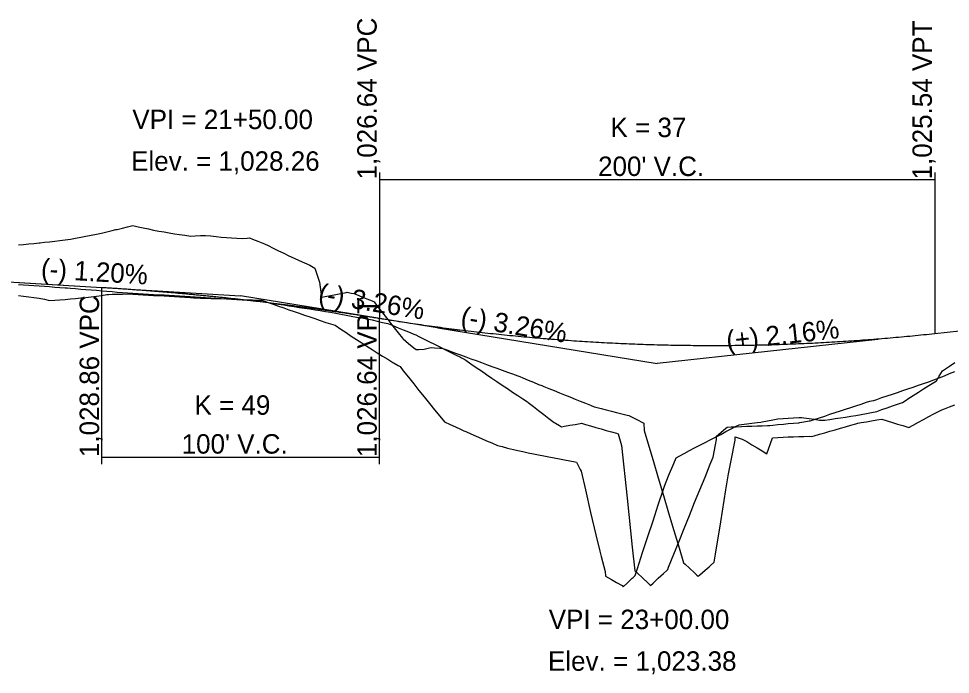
# Model space of a CAD drawing. Extents: x 1590191 to 1593577, y 1108634 to 1115609.
# Drawn here: x 1591349 to 1591684.7, y 1114898.4 to 1115134.6 of the extents above; entities that cross this region are included whole.
import ezdxf

# ---------------------------------------------------------------- set-up
doc = ezdxf.new("R2010")
doc.units = 0
for name, color, linetype in [('BR_EXIST_GROUND_LT', 7, 'Continuous'), ('BR_EXIST_GROUND_RT', 7, 'Continuous'), ('RD_DDB_GradeTX', 7, 'Continuous'), ('RD_DDB_Profile_EX', 7, 'Continuous'), ('RD_DDB_Profile_Lbl', 7, 'Continuous'), ('RD_DDB_Profile_PR', 7, 'Continuous'), ('RD_DDB_StripGrade', 7, 'Continuous'), ('RD_DDB_VCLbl', 7, 'Continuous')]:
    doc.layers.add(name, color=color, linetype=linetype)

msp = doc.modelspace()

# ---------------------------------------------------------------- linework, layer by layer
at = {"layer": 'BR_EXIST_GROUND_LT'}
msp.add_lwpolyline([(1591348.93, 1115034.88), (1591350.81, 1115034.64), (1591352.68, 1115034.4), (1591354.56, 1115034.18), (1591356.43, 1115033.94), (1591358.3, 1115033.49), (1591360.18, 1115033.11), (1591362.05, 1115033.22), (1591363.93, 1115033.34), (1591365.8, 1115033.48), (1591367.67, 1115033.64), (1591369.55, 1115033.81), (1591371.42, 1115034), (1591373.3, 1115034.2), (1591375.17, 1115034.42), (1591377.04, 1115034.66), (1591378.92, 1115034.91), (1591380.79, 1115035.18), (1591381.45, 1115035.28), (1591382.67, 1115035.3), (1591384.54, 1115035.34), (1591386.41, 1115035.38), (1591388.29, 1115035.42), (1591390.16, 1115035.31), (1591392.04, 1115035.2), (1591393.91, 1115035.09), (1591395.78, 1115035), (1591397.66, 1115034.91), (1591399.53, 1115034.83), (1591401.41, 1115034.75), (1591401.93, 1115034.74), (1591403.28, 1115034.63), (1591405.15, 1115034.49), (1591407.03, 1115034.35), (1591408.9, 1115034.22), (1591410.78, 1115034.1), (1591412.08, 1115034.01), (1591412.65, 1115034), (1591414.52, 1115033.94), (1591416.4, 1115033.88), (1591418.27, 1115033.83), (1591420.15, 1115033.79), (1591422.02, 1115033.75), (1591423.89, 1115033.66), (1591425.77, 1115033.58), (1591427.64, 1115033.5), (1591429.52, 1115033.43), (1591431.39, 1115033.36), (1591433.26, 1115033.3), (1591435.14, 1115033.24), (1591436.14, 1115033.22), (1591436.59, 1115033.21), (1591437.01, 1115033.06), (1591438.89, 1115032.39), (1591440.76, 1115031.72), (1591442.63, 1115031.06), (1591444.51, 1115030.4), (1591446.38, 1115029.75), (1591448.26, 1115029.1), (1591450.13, 1115028.46), (1591452, 1115027.82), (1591453.88, 1115027.19), (1591455.75, 1115026.56), (1591457.63, 1115025.89), (1591459.64, 1115025.18), (1591461.37, 1115024.67), (1591463.02, 1115024.18), (1591465.12, 1115022.74), (1591467, 1115021.48), (1591468.87, 1115020.23), (1591470.74, 1115019), (1591472.62, 1115017.79), (1591474.49, 1115016.6), (1591476.37, 1115015.43), (1591476.69, 1115015.22), (1591478.24, 1115014.24), (1591480.11, 1115013.07), (1591481.99, 1115011.92), (1591483.86, 1115010.78), (1591484.28, 1115010.54), (1591485.74, 1115009.69), (1591486.45, 1115009.27), (1591487.61, 1115007.78), (1591489.48, 1115005.39), (1591491.36, 1115003.02), (1591493.23, 1115000.66), (1591495.11, 1114998.32), (1591496.98, 1114996), (1591498.85, 1114993.7), (1591500.73, 1114991.41), (1591502.45, 1114989.33), (1591504.48, 1114988.41), (1591506.35, 1114987.55), (1591508.22, 1114986.71), (1591509.46, 1114986.16), (1591510.1, 1114985.87), (1591511.97, 1114985.04), (1591513.85, 1114984.21), (1591515.72, 1114983.39), (1591517.59, 1114982.57), (1591519.47, 1114981.77), (1591521.59, 1114980.86), (1591523.22, 1114980.42), (1591525.09, 1114979.93), (1591527.24, 1114979.37), (1591528.84, 1114979.03), (1591530.71, 1114978.63), (1591532.59, 1114978.23), (1591534.46, 1114977.85), (1591536.33, 1114977.46), (1591538.21, 1114977.08), (1591540.08, 1114976.71), (1591541.96, 1114976.34), (1591543.83, 1114975.98), (1591545.7, 1114975.62), (1591547.58, 1114975.27), (1591549.45, 1114974.92), (1591549.98, 1114974.83), (1591551.33, 1114972.16), (1591551.64, 1114971.54), (1591553.2, 1114964.82), (1591555.07, 1114956.75), (1591556.95, 1114948.7), (1591558.34, 1114942.75), (1591558.82, 1114940.9), (1591560.27, 1114935.41), (1591560.43, 1114933.79), (1591562.57, 1114932.57), (1591564.44, 1114931.5), (1591566.38, 1114930.4), (1591566.84, 1114929.95), (1591568.19, 1114931.23), (1591570.07, 1114933), (1591570.41, 1114933.33), (1591571.13, 1114934.06), (1591571.94, 1114936.53), (1591573.81, 1114942.28), (1591575.69, 1114948.01), (1591577.56, 1114953.73), (1591579.44, 1114959.44), (1591581.31, 1114965.13), (1591581.67, 1114966.23), (1591583.18, 1114969.89), (1591585.06, 1114974.41), (1591585.87, 1114976.37), (1591586.93, 1114976.95), (1591588.81, 1114977.99), (1591590.68, 1114979.02), (1591592.55, 1114979.99), (1591594.43, 1114980.96), (1591596.3, 1114981.93), (1591598.18, 1114982.9), (1591600.05, 1114983.87), (1591601.92, 1114984.85), (1591603.8, 1114985.82), (1591605.67, 1114986.79), (1591607.55, 1114987.77), (1591608.58, 1114988.3), (1591609.42, 1114988.41), (1591611.29, 1114988.65), (1591613.17, 1114988.88), (1591615.04, 1114989.12), (1591616.43, 1114989.29), (1591616.92, 1114989.38), (1591618.79, 1114989.73), (1591620.66, 1114990.07), (1591622.57, 1114990.42), (1591624.41, 1114990.54), (1591626.29, 1114990.66), (1591628.16, 1114990.78), (1591630.03, 1114990.9), (1591631.05, 1114990.96), (1591631.91, 1114990.84), (1591633.78, 1114990.57), (1591635.66, 1114990.3), (1591637.53, 1114990.02), (1591638.94, 1114989.92), (1591639.4, 1114989.98), (1591641.28, 1114990.25), (1591643.15, 1114990.53), (1591645.03, 1114990.8), (1591646.9, 1114991.08), (1591648.77, 1114991.37), (1591650.65, 1114991.67), (1591652.52, 1114992.03), (1591654.4, 1114992.39), (1591656.27, 1114992.76), (1591658.14, 1114993.14), (1591660.02, 1114993.79), (1591661.89, 1114994.45), (1591663.77, 1114995.1), (1591665.64, 1114995.76), (1591667.39, 1114996.36), (1591668.69, 1114997.22), (1591669.39, 1114997.67), (1591671.26, 1114998.88), (1591673.14, 1115000.08), (1591675.01, 1115001.26), (1591676.88, 1115002.42), (1591678.76, 1115003.58), (1591679.63, 1115004.1), (1591680.63, 1115005.78), (1591681.82, 1115007.75), (1591682.51, 1115008.22), (1591684.38, 1115009.46), (1591686.25, 1115010.68)], dxfattribs=at)
at = {"layer": 'BR_EXIST_GROUND_RT'}
msp.add_lwpolyline([(1591348.93, 1115053.14), (1591350.81, 1115053.28), (1591352.68, 1115053.45), (1591354.56, 1115053.63), (1591356.43, 1115053.83), (1591356.79, 1115053.87), (1591358.3, 1115054.02), (1591360.18, 1115054.22), (1591362.05, 1115054.44), (1591363.93, 1115054.67), (1591365.8, 1115054.92), (1591367.69, 1115055.19), (1591369.55, 1115055.51), (1591371.42, 1115055.85), (1591373.3, 1115056.2), (1591375.17, 1115056.57), (1591377.04, 1115056.96), (1591378.92, 1115057.37), (1591380.79, 1115057.79), (1591382.67, 1115058.23), (1591384.1, 1115058.58), (1591384.54, 1115058.68), (1591386.41, 1115059.13), (1591388.29, 1115059.59), (1591390.16, 1115060.04), (1591392.04, 1115059.62), (1591393.91, 1115059.21), (1591395.78, 1115058.82), (1591397.66, 1115058.44), (1591399.53, 1115058.09), (1591401.41, 1115057.75), (1591403.28, 1115057.42), (1591405.15, 1115057.12), (1591407.03, 1115056.83), (1591408.9, 1115056.56), (1591411.04, 1115056.27), (1591412.65, 1115056.33), (1591414.52, 1115056.42), (1591416.4, 1115056.51), (1591418.27, 1115056.3), (1591420.15, 1115056.11), (1591422.02, 1115055.93), (1591423.89, 1115055.77), (1591425.77, 1115055.62), (1591427.64, 1115055.48), (1591429.56, 1115055.36), (1591431.39, 1115055.55), (1591432.17, 1115055.64), (1591433.26, 1115055.2), (1591435.14, 1115054.44), (1591437.01, 1115053.71), (1591437.57, 1115053.49), (1591438.89, 1115052.83), (1591440.76, 1115051.9), (1591442.63, 1115050.99), (1591444.51, 1115050.08), (1591446.38, 1115049.19), (1591448.26, 1115048.31), (1591450.13, 1115047.44), (1591452, 1115046.58), (1591453.88, 1115045.73), (1591455.75, 1115044.65), (1591457.47, 1115039.69), (1591458.14, 1115034.21), (1591459.5, 1115034.47), (1591461.37, 1115034.83), (1591463.25, 1115035.2), (1591465.12, 1115035.58), (1591467, 1115035.97), (1591467.37, 1115036.05), (1591468.87, 1115035.75), (1591469.78, 1115035.57), (1591470.74, 1115035.18), (1591472.62, 1115034.44), (1591474.49, 1115033.7), (1591476.37, 1115032.97), (1591477.13, 1115032.53), (1591478.24, 1115031.08), (1591480.11, 1115028.64), (1591481.99, 1115026.22), (1591483.86, 1115023.81), (1591485.74, 1115021.43), (1591487.27, 1115019.49), (1591487.61, 1115019.2), (1591489.48, 1115017.61), (1591491.36, 1115016.04), (1591492.18, 1115015.36), (1591493.23, 1115015.41), (1591495.11, 1115015.51), (1591496.98, 1115015.97), (1591497.71, 1115016.15), (1591498.85, 1115016.06), (1591500.73, 1115015.9), (1591501.49, 1115015.93), (1591502.6, 1115015.53), (1591503.59, 1115015.18), (1591504.48, 1115014.85), (1591506.35, 1115014.15), (1591507.09, 1115013.88), (1591508.22, 1115013.46), (1591510.1, 1115012.77), (1591511.97, 1115012.09), (1591513.85, 1115011.4), (1591515.72, 1115010.71), (1591517.59, 1115010.03), (1591519.47, 1115009.34), (1591521.34, 1115008.65), (1591523.22, 1115007.97), (1591525.09, 1115007.28), (1591526.96, 1115006.59), (1591528.84, 1115005.91), (1591529.57, 1115005.64), (1591530.71, 1115005.17), (1591532.59, 1115004.4), (1591534.46, 1115003.63), (1591536.33, 1115002.86), (1591537.48, 1115002.39), (1591538.21, 1115002.1), (1591540.08, 1115001.35), (1591541.96, 1115000.59), (1591543.83, 1114999.84), (1591545.7, 1114999.08), (1591547.58, 1114998.33), (1591549.45, 1114997.58), (1591551.33, 1114996.82), (1591553.2, 1114996.07), (1591555.07, 1114995.32), (1591556.34, 1114994.81), (1591556.95, 1114994.65), (1591558.82, 1114994.18), (1591560.7, 1114993.7), (1591562.57, 1114993.23), (1591564.44, 1114992.76), (1591566.32, 1114992.28), (1591568.19, 1114991.81), (1591568.89, 1114991.63), (1591570.07, 1114991.02), (1591571.94, 1114990.05), (1591573.81, 1114989.08), (1591574.25, 1114988.85), (1591574.38, 1114986.24), (1591575.69, 1114981.82), (1591577.56, 1114975.49), (1591579.44, 1114969.17), (1591581.31, 1114962.86), (1591583.18, 1114956.56), (1591585.06, 1114950.26), (1591586.93, 1114943.97), (1591588.49, 1114938.58), (1591589.08, 1114938.05), (1591590.68, 1114936.6), (1591592.55, 1114934.92), (1591593.39, 1114934.17), (1591593.86, 1114933.73), (1591594.43, 1114934.23), (1591596.3, 1114935.88), (1591597.74, 1114937.15), (1591598.18, 1114937.54), (1591599.57, 1114938.77), (1591600.05, 1114941.75), (1591601.92, 1114953.35), (1591603.8, 1114964.9), (1591604.73, 1114970.61), (1591605.67, 1114975.45), (1591607.1, 1114982.74), (1591607.16, 1114983.91), (1591607.55, 1114983.8), (1591609.68, 1114983.17), (1591611.29, 1114982.23), (1591613.17, 1114981.13), (1591615.04, 1114980.01), (1591616.92, 1114978.87), (1591618.54, 1114977.87), (1591620.6, 1114983.65), (1591622.54, 1114983.74), (1591624.41, 1114983.82), (1591626.29, 1114983.9), (1591628.16, 1114983.97), (1591630.03, 1114984.04), (1591631.91, 1114984.11), (1591633.78, 1114984.15), (1591634.73, 1114984.05), (1591635.66, 1114984.33), (1591637.53, 1114984.88), (1591639.4, 1114985.43), (1591641.28, 1114985.98), (1591643.15, 1114986.52), (1591645.03, 1114987.06), (1591646.9, 1114987.59), (1591648.77, 1114988.12), (1591650.65, 1114988.65), (1591651.38, 1114988.85), (1591652.52, 1114989.06), (1591654.4, 1114989.39), (1591656.27, 1114989.72), (1591658.14, 1114990.04), (1591660.02, 1114990.32), (1591661.89, 1114989.74), (1591663.77, 1114989.16), (1591665.64, 1114988.57), (1591667.51, 1114987.98), (1591669.68, 1114987.29), (1591671.26, 1114988.18), (1591673.14, 1114989.21), (1591675.01, 1114990.23), (1591676.88, 1114991.23), (1591678.76, 1114992.22), (1591680.63, 1114993.2), (1591681.58, 1114993.69), (1591682.51, 1114994.06), (1591684.38, 1114994.79), (1591686.25, 1114995.52)], dxfattribs=at)
at = {"layer": 'RD_DDB_GradeTX'}
for p, q in [((1591349.16, 1115039.59), (1591429.01, 1115034.79)), ((1591507.97, 1115021.94), (1591429.01, 1115034.79)), ((1591500.05, 1115023.23), (1591579.01, 1115010.38)), ((1591658.55, 1115018.98), (1591579.01, 1115010.38))]:
    msp.add_line(p, q, dxfattribs=at)
at = {"layer": 'RD_DDB_Profile_EX'}
msp.add_lwpolyline([(1591348.93, 1115038.86), (1591350.81, 1115038.73), (1591352.68, 1115038.59), (1591354.56, 1115038.46), (1591356.43, 1115038.32), (1591358.33, 1115038.18), (1591360.18, 1115038.05), (1591362.05, 1115037.91), (1591363.93, 1115037.78), (1591365.8, 1115037.64), (1591366.58, 1115037.58), (1591367.67, 1115037.5), (1591369.55, 1115037.35), (1591371.42, 1115037.2), (1591373.3, 1115037.04), (1591375.17, 1115036.89), (1591377.04, 1115036.73), (1591379.1, 1115036.56), (1591380.79, 1115036.42), (1591382.67, 1115036.27), (1591384.54, 1115036.12), (1591386.41, 1115035.96), (1591388.29, 1115035.8), (1591389.7, 1115035.68), (1591390.16, 1115035.66), (1591392.04, 1115035.56), (1591393.91, 1115035.46), (1591395.78, 1115035.36), (1591397.66, 1115035.26), (1591399.53, 1115035.15), (1591400.76, 1115035.08), (1591401.41, 1115035.05), (1591403.28, 1115034.94), (1591405.15, 1115034.83), (1591407.03, 1115034.72), (1591408.9, 1115034.61), (1591410.78, 1115034.5), (1591412.65, 1115034.39), (1591414.67, 1115034.26), (1591416.4, 1115034.15), (1591418.27, 1115034.03), (1591420.15, 1115033.9), (1591422.02, 1115033.78), (1591423.89, 1115033.65), (1591425.77, 1115033.53), (1591427.64, 1115033.4), (1591429.52, 1115033.27), (1591431.39, 1115033.14), (1591433.26, 1115033.01), (1591435.25, 1115032.87), (1591437.01, 1115032.6), (1591438.89, 1115032.32), (1591440.76, 1115032.04), (1591442.63, 1115031.75), (1591444.51, 1115031.47), (1591446.38, 1115031.18), (1591448.26, 1115030.89), (1591450.13, 1115030.6), (1591452, 1115030.31), (1591453.88, 1115030.01), (1591455.84, 1115029.7), (1591457.63, 1115029.44), (1591459.52, 1115029.15), (1591461.37, 1115028.84), (1591463.28, 1115028.51), (1591465.12, 1115028.17), (1591467, 1115027.82), (1591468.87, 1115027.46), (1591470.74, 1115027.11), (1591472.62, 1115026.76), (1591474.49, 1115026.41), (1591476.37, 1115026.05), (1591478.24, 1115025.62), (1591480.11, 1115025.19), (1591481.99, 1115024.75), (1591483.86, 1115024), (1591485.74, 1115023.25), (1591487.61, 1115022.5), (1591489.48, 1115021.74), (1591491.36, 1115020.99), (1591492.09, 1115020.7), (1591493.23, 1115020.12), (1591495.11, 1115019.18), (1591496.98, 1115018.23), (1591498.85, 1115017.29), (1591500.73, 1115016.35), (1591502.6, 1115015.41), (1591504.48, 1115014.47), (1591506.35, 1115013.53), (1591508.22, 1115012.61), (1591508.55, 1115012.47), (1591509.78, 1115011.82), (1591510.1, 1115011.59), (1591511.97, 1115010.28), (1591513.85, 1115008.97), (1591515.72, 1115007.67), (1591517.59, 1115006.38), (1591519.47, 1115005.1), (1591521.34, 1115003.83), (1591523.22, 1115002.57), (1591525.09, 1115001.31), (1591526.96, 1115000.06), (1591528.84, 1114998.83), (1591530.71, 1114997.6), (1591532.28, 1114996.57), (1591532.59, 1114996.34), (1591534.46, 1114994.88), (1591536.33, 1114993.44), (1591538.21, 1114992.01), (1591540.08, 1114990.58), (1591541.96, 1114989.16), (1591542.4, 1114988.83), (1591543.83, 1114988.01), (1591544.54, 1114987.61), (1591545.7, 1114987.8), (1591547.58, 1114988.11), (1591549.45, 1114988.42), (1591551.33, 1114988.74), (1591551.77, 1114988.82), (1591553.2, 1114988.4), (1591555.07, 1114987.86), (1591556.95, 1114987.32), (1591558.82, 1114986.79), (1591560.7, 1114986.27), (1591562.57, 1114985.75), (1591564.44, 1114985.24), (1591565.02, 1114985.08), (1591566.18, 1114980.89), (1591568.19, 1114961.91), (1591570.07, 1114944.23), (1591570.98, 1114935.64), (1591571.35, 1114935.44), (1591571.94, 1114934.88), (1591573.81, 1114933.13), (1591575.69, 1114931.37), (1591576.68, 1114930.45), (1591577.56, 1114931.29), (1591577.93, 1114931.65), (1591579.44, 1114933.03), (1591581.31, 1114934.74), (1591582.5, 1114935.83), (1591582.86, 1114936.17), (1591583.18, 1114936.98), (1591585.06, 1114941.67), (1591586.93, 1114946.34), (1591588.81, 1114951), (1591590.68, 1114955.64), (1591592.55, 1114960.27), (1591594.43, 1114964.88), (1591596.3, 1114969.48), (1591598.18, 1114974.06), (1591599.21, 1114976.58), (1591600.05, 1114981.1), (1591600.4, 1114982.98), (1591600.45, 1114984.23), (1591601.92, 1114985.47), (1591603.8, 1114987.05), (1591604.29, 1114987.46), (1591605.67, 1114987.52), (1591607.55, 1114987.6), (1591609.42, 1114987.67), (1591611.29, 1114987.75), (1591613.17, 1114987.82), (1591615.04, 1114987.9), (1591616.92, 1114987.97), (1591618.79, 1114988.05), (1591619.65, 1114988.08), (1591620.66, 1114988.18), (1591622.54, 1114988.37), (1591624.54, 1114988.57), (1591626.29, 1114988.72), (1591628.16, 1114988.88), (1591630.03, 1114989.04), (1591630.4, 1114989.07), (1591631.91, 1114989.34), (1591633.78, 1114989.66), (1591634.18, 1114989.73), (1591635.66, 1114990.22), (1591637.53, 1114990.83), (1591639.4, 1114991.45), (1591641.28, 1114992.07), (1591643.15, 1114992.69), (1591645.03, 1114993.3), (1591646.9, 1114993.92), (1591648.77, 1114994.54), (1591650.65, 1114995.16), (1591652.52, 1114995.78), (1591654.4, 1114996.39), (1591655.69, 1114996.82), (1591656.27, 1114996.93), (1591657.04, 1114997.08), (1591658.14, 1114997.45), (1591660.02, 1114998.08), (1591661.89, 1114998.71), (1591663.77, 1114999.34), (1591665.64, 1114999.97), (1591667.51, 1115000.61), (1591669.39, 1115001.24), (1591671.26, 1115001.87), (1591673.14, 1115002.51), (1591675.01, 1115003.15), (1591676.88, 1115003.79), (1591678.36, 1115004.32), (1591678.76, 1115004.48), (1591680.63, 1115005.23), (1591682.51, 1115005.98), (1591684.38, 1115006.73), (1591686.25, 1115007.48)], dxfattribs=at)
at = {"layer": 'RD_DDB_Profile_PR'}
for p, q in [((1591199.01, 1115048.59), (1591379.01, 1115037.79)), ((1591679.01, 1115021.19), (1591829.01, 1115037.41))]:
    msp.add_line(p, q, dxfattribs=at)
for points in [[(1591379.01, 1115037.79), (1591381.01, 1115037.67), (1591383.01, 1115037.55), (1591385.01, 1115037.42), (1591387.01, 1115037.28), (1591389.01, 1115037.14), (1591391.01, 1115037), (1591393.01, 1115036.85), (1591395.01, 1115036.7), (1591397.01, 1115036.55), (1591399.01, 1115036.39), (1591401.01, 1115036.23), (1591403.01, 1115036.06), (1591405.01, 1115035.89), (1591407.01, 1115035.71), (1591409.01, 1115035.53), (1591411.01, 1115035.35), (1591413.01, 1115035.16), (1591415.01, 1115034.97), (1591417.01, 1115034.77), (1591419.01, 1115034.57), (1591421.01, 1115034.37), (1591423.01, 1115034.16), (1591425.01, 1115033.95), (1591427.01, 1115033.73), (1591429.01, 1115033.51), (1591431.01, 1115033.29), (1591433.01, 1115033.06), (1591435.01, 1115032.82), (1591437.01, 1115032.59), (1591439.01, 1115032.34), (1591441.01, 1115032.1), (1591443.01, 1115031.85), (1591445.01, 1115031.6), (1591447.01, 1115031.34), (1591449.01, 1115031.08), (1591451.01, 1115030.81), (1591453.01, 1115030.54), (1591455.01, 1115030.27), (1591457.01, 1115029.99), (1591459.01, 1115029.71), (1591461.01, 1115029.42), (1591463.01, 1115029.13), (1591465.01, 1115028.83), (1591467.01, 1115028.54), (1591469.01, 1115028.23), (1591471.01, 1115027.93), (1591473.01, 1115027.61), (1591475.01, 1115027.3), (1591477.01, 1115026.98), (1591479.01, 1115026.66)], [(1591479.01, 1115026.66), (1591483.01, 1115026.02), (1591487.01, 1115025.4), (1591491.01, 1115024.8), (1591495.01, 1115024.23), (1591499.01, 1115023.67), (1591503.01, 1115023.14), (1591507.01, 1115022.63), (1591511.01, 1115022.14), (1591515.01, 1115021.67), (1591519.01, 1115021.23), (1591523.01, 1115020.81), (1591527.01, 1115020.4), (1591531.01, 1115020.02), (1591535.01, 1115019.67), (1591539.01, 1115019.33), (1591543.01, 1115019.01), (1591547.01, 1115018.72), (1591551.01, 1115018.45), (1591555.01, 1115018.2), (1591559.01, 1115017.97), (1591563.01, 1115017.76), (1591567.01, 1115017.58), (1591571.01, 1115017.41), (1591575.01, 1115017.27), (1591579.01, 1115017.15), (1591583.01, 1115017.05), (1591587.01, 1115016.98), (1591591.01, 1115016.92), (1591595.01, 1115016.89), (1591599.01, 1115016.88), (1591603.01, 1115016.89), (1591607.01, 1115016.92), (1591611.01, 1115016.97), (1591615.01, 1115017.05), (1591619.01, 1115017.14), (1591623.01, 1115017.26), (1591627.01, 1115017.4), (1591631.01, 1115017.56), (1591635.01, 1115017.74), (1591639.01, 1115017.95), (1591643.01, 1115018.18), (1591647.01, 1115018.42), (1591651.01, 1115018.69), (1591655.01, 1115018.99), (1591659.01, 1115019.3), (1591663.01, 1115019.63), (1591667.01, 1115019.99), (1591671.01, 1115020.37), (1591675.01, 1115020.77), (1591679.01, 1115021.19)]]:
    msp.add_spline(points, degree=3, dxfattribs=at)
at = {"layer": 'RD_DDB_VCLbl'}
for p, q in [((1591479.01, 1115079.16), (1591479.01, 1115026.66)), ((1591679.01, 1115079.16), (1591679.01, 1115021.19)), ((1591479.01, 1115076.66), (1591679.01, 1115076.66)), ((1591379.01, 1114974.16), (1591379.01, 1115037.79)), ((1591479.01, 1114974.16), (1591479.01, 1115026.66)), ((1591379.01, 1114976.66), (1591479.01, 1114976.66))]:
    msp.add_line(p, q, dxfattribs=at)

# ---------------------------------------------------------------- texts
at = {"layer": 'RD_DDB_GradeTX'}
for s, rotation, p in [('(-) 1.20%', 356.5664, (1591356.94, 1115041.12)), ('(-) 3.26%', 350.7555, (1591456.65, 1115032.32)), ('(-) 3.26%', 350.7555, (1591507.95, 1115023.97)), ('(+) 2.16%', 6.1697, (1591604.32, 1115015.13))]:
    msp.add_text(s, height=7, rotation=rotation, dxfattribs=at).set_placement(p)
at = {"layer": 'RD_DDB_Profile_Lbl'}
for s, p in [('VPI = 21+50.00', (1591389.99, 1115094.79)), ('Elev. = 1,028.26', (1591389.55, 1115079.79)), ('VPI = 23+00.00', (1591539.99, 1114914.7)), ('Elev. = 1,023.38', (1591539.71, 1114899.7))]:
    msp.add_text(s, height=7, dxfattribs=at).set_placement(p)
at = {"layer": 'RD_DDB_StripGrade'}
for s, p in [('1,026.64 VPC', (1591478.01, 1115076.66)), ('1,025.54 VPT', (1591678.01, 1115076.66)), ('1,028.86 VPC', (1591378.01, 1114976.66)), ('1,026.64 VPT', (1591478.01, 1114976.66))]:
    msp.add_text(s, height=7, rotation=90, dxfattribs=at).set_placement(p)
at = {"layer": 'RD_DDB_VCLbl'}
for s, p in [('K = 37', (1591562.23, 1115091.91)), ("200' V.C.", (1591557.76, 1115077.91)), ('K = 49', (1591412.39, 1114991.91)), ("100' V.C.", (1591407.76, 1114977.91))]:
    msp.add_text(s, height=7, dxfattribs=at).set_placement(p)

doc.saveas('drawing.dxf')
